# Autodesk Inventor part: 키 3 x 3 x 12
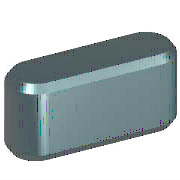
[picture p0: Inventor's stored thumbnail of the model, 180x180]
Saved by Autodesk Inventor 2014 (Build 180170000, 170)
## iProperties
Created: 2012-02
Part Number: 키 3 x 3 x 12
Material: 강철, 연강
Description: 키 및 해당 키홈
Document SubType Name: Modeling
Standard: KS B 1311
Designer: mduedu
Standards Organization: KS
Language: ko-KR
Size Designation: 3 x 3 x 12
Categories: <MemberInstance><Categories><Category DisplayName="샤프트 부품" InternalName="7f7aeb1f-a693-4053-b835-cee3144e0d98" Mnemonic="SHFT"><Category DisplayName="키" Interna
Density: 1 g/cm^3
Appearance: Steel
IsCustomPart: 1
Author: mduedu
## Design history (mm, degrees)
sketch "스케치1"
  geometry: L1 (1.5, 1.5)-(10.5, 1.5); L2 (10.5, -1.5)-(1.5, -1.5); L3 (0, 9.4)-(0, -7.4) reference; L4 (-5, 0)-(30, 0) reference; L5 (12, 0)-(12, 7); A1 r 1.5 centre (1.5, 0) between (1.5, 1.5) and (1.5, -1.5); A2 r 1.5 centre (10.5, 0) between (10.5, -1.5) and (10.5, 1.5)
  constraints: 6 end point, 5 point on circle, 4 tangent, 3 point on line, 2 centre point, 1 horizontal, 1 parallel, 1 perpendicular
  dimensions: "d0" = 1.5 radius of A1 (= 0.5 x PB); "d13" = 1.5 radius of A2 (= 0.5 x PB); "d14" = 12 distance between parallel lines of L5 L3 (= NLG)
extrude "본체1" new body sketch "스케치1" taper "d3" = 0 deg; stored distance "d4" = 10
workplane "Work Plane3"
body "Solid1"
workplane "Work Plane1"
workplane "Work Plane2"
chamfer "모따기1" distance "d8" = 0.25 (= PHH); stored, may be unused: second distance "d9" = 0.25 (= PHH), angle "d15" = 45 deg
other parameters: "d1" = -1.8 (= -PNT), "d2" = 1.2 (= PH - PNT), "NLG" = 12 [user parameter; used in 3 equation terms], "PB" = 3 [user parameter; used in 2 equation terms], "PNT" = 1.8 [user parameter; used in 2 equation terms], "PH" = 3 [user parameter; used in 1 equation term], "PHH" = 0.25 [user parameter; used in 2 equation terms], "d10" = 0, "d16" = 0, "d17" = 0, "d18" = 0, "WDMIN" = 8 [user parameter], "PLB2" = 12 (= NLG) [user parameter], "PLB1" = 12 (= NLG) [user parameter], "RR" = 0.08 [user parameter], "PUEB" = 1.4 [user parameter]
